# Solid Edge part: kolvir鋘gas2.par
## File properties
Author: Türk
Template: Iso Part.par
Last saved by: Türk
Revision: 5
Application: Solid Edge
Accuracy: 0,990
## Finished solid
Body 1: solid body, 4 faces, 4 edges, 0 vertices.
  Faces by surface: cylinder 2, plane 2
  Edges by curve: circle 4
Bounding box of the edges (mm): 88.000 x 1.000 x 88.000, from (-44, 1.5, -44) to (44, 2.5, 44).
Cylindrical faces by radius (mm): R41.5 x1, R44 x1
Planar faces by outward normal: +y 1, -y 1
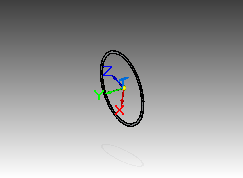
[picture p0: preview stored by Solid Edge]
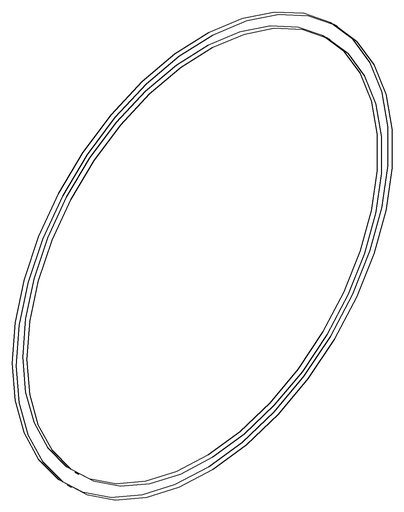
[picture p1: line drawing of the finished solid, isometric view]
